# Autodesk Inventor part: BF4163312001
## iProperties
Shininess: 64.0
Angle Display Precision: 2
Document Length Units: 11272
Document Angle Units: 11279
Document Time Units: 11290
Document Mass Units: 11286
Document Length Units Precision: 3
Document Angle Units Precision: 2
Created: 2003-05
Part Number: BF4163312001
Material: Bronze, Soft Tin
Description: 1/8 UNION, 125 LB RED BRASS, NPT
Vendor: BF4163312001
Document SubType Name: Modeling
Designer: RCOPE
Density: 8.874
Volumn: 18.308120108166392
Area: 61.30147967188873
PropertySet Name: Model Information
Control State: 0
Master: False
Checked Out: False
Title: UNION, 125 LB RED BRASS, NPT
Author: RCOPE
Revision Number: 0
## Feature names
1. Extrusion1
2. Extrusion2
3. Extrusion3
4. Extrusion4
5. Extrusion5
6. Extrusion6
